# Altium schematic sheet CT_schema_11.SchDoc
size 147 x 119 mm
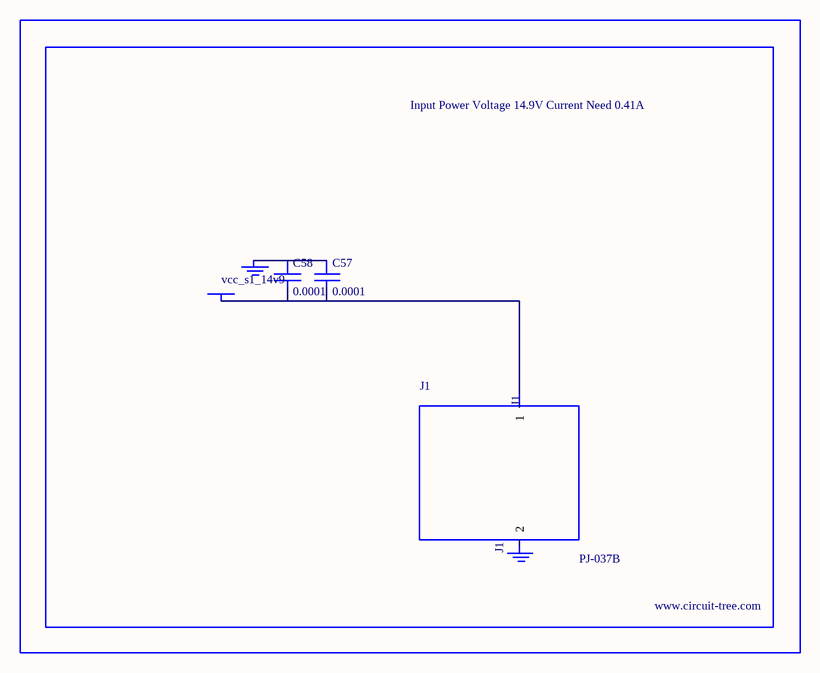
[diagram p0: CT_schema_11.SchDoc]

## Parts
BORDER10  (no value)
C57  0.0001  [EXV-9H]
C58  0.0001  [EXV-9H]
GND_INSTANCE_10_0  (no value)
GND_INSTANCE_10_1  (no value)
J1  PJ-037B  [PJ-037B_PACKAGE]
POWER_INSTANCE_10_0  vcc_s1_14v9

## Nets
NetC57_1: C57.1 C58.1 GND_INSTANCE_10_0.0(GND)
NetC57_2: C57.2 C58.2 J1.1 POWER_INSTANCE_10_0.0(PWR)

Not connected (* = marked no-connect by the designer): GND_INSTANCE_10_1 0(GND); J1 2

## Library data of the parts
BORDER10 = BORDER_PAGE10
C57 C58 = EDK107M035A9HAA
GND_INSTANCE_10_0 GND_INSTANCE_10_1 = GND
POWER_INSTANCE_10_0 = PWR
